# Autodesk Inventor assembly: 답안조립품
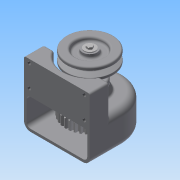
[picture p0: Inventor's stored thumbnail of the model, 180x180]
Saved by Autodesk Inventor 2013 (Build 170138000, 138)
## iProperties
Created: 2015-02
Part Number: 답안조립품
Document SubType Name: Assembly
Designer: Administrator
Author: Administrator
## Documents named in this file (14)
- C:\Documents and Settings\Administrator\바탕 화면\450214V1004\답안조립품.iam
- C:\Documents and Settings\Administrator\바탕 화면\450214V1004\1-본체.ipt
- C:\Documents and Settings\Administrator\바탕 화면\450214V1004\베어링 6001.ipt
- C:\Documents and Settings\Administrator\바탕 화면\450214V1004\축.ipt
- C:\Documents and Settings\Administrator\바탕 화면\450214V1004\키5x5.ipt
- C:\Documents and Settings\Administrator\바탕 화면\450214V1004\M3x0.5.ipt
- C:\Documents and Settings\Administrator\바탕 화면\450214V1004\5-스퍼기어.ipt
- C:\Documents and Settings\Administrator\바탕 화면\450214V1004\오일실.ipt
- C:\Documents and Settings\Administrator\바탕 화면\450214V1004\축커버.ipt
- C:\Documents and Settings\Administrator\바탕 화면\450214V1004\와샤.ipt
- C:\Documents and Settings\Administrator\바탕 화면\450214V1004\키4x4.ipt
- C:\Documents and Settings\Administrator\바탕 화면\450214V1004\M5x0.8.ipt
- M5x0.8.ipt
- C:\Documents and Settings\Administrator\바탕 화면\450214V1004\4-v-벨트풀리.ipt
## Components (7 placed, 4 different names)
1. 1-본체:1
2. M5x0.8:1
3. 4-v-벨트풀리:1 — 각도:4
4. M3x0.5:1
5. M3x0.5:2
6. M3x0.5:3
7. M3x0.5:4
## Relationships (1: Angle 1)
- 각도:4 [Angle]: 4-v-벨트풀리:1
